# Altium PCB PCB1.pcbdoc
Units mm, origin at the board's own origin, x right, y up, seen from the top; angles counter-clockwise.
Board outline 216.66 x 148.21 mm, 2 copper layers (Top Layer, Bottom Layer); 59 components, 30 nets, 163 pads, 96 vias.
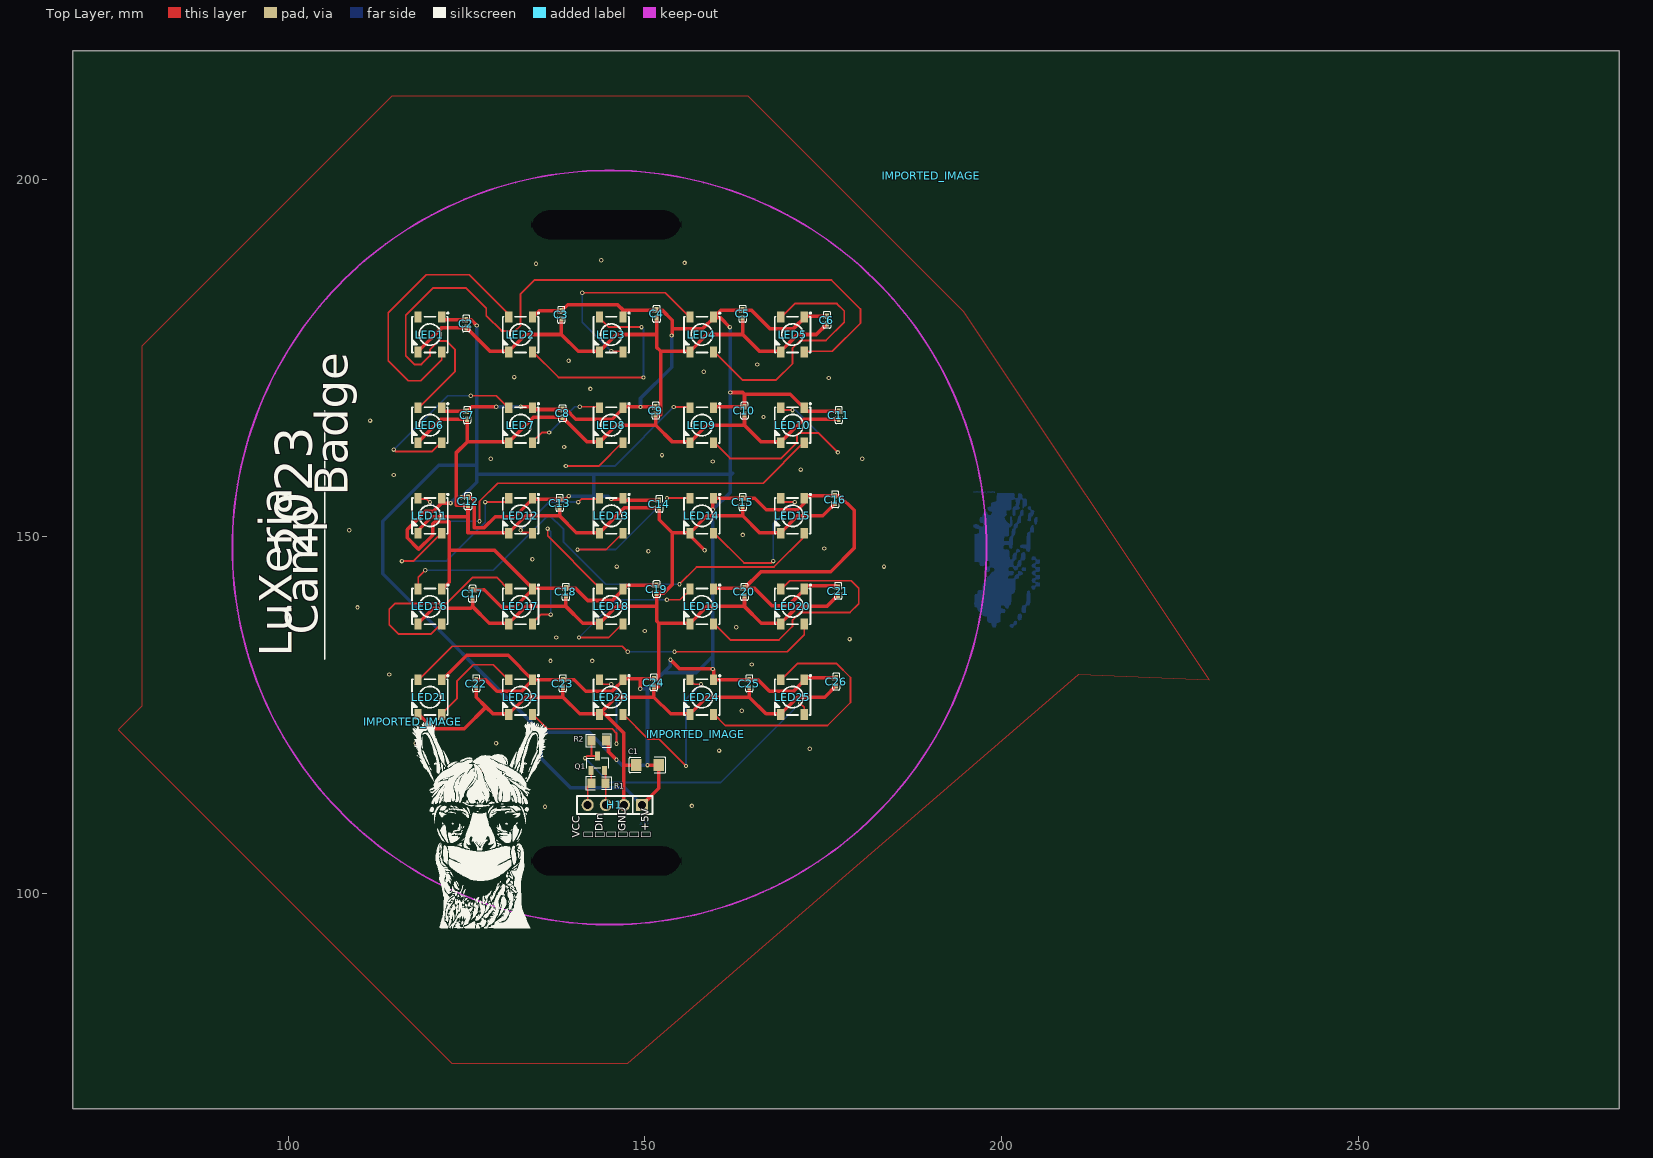
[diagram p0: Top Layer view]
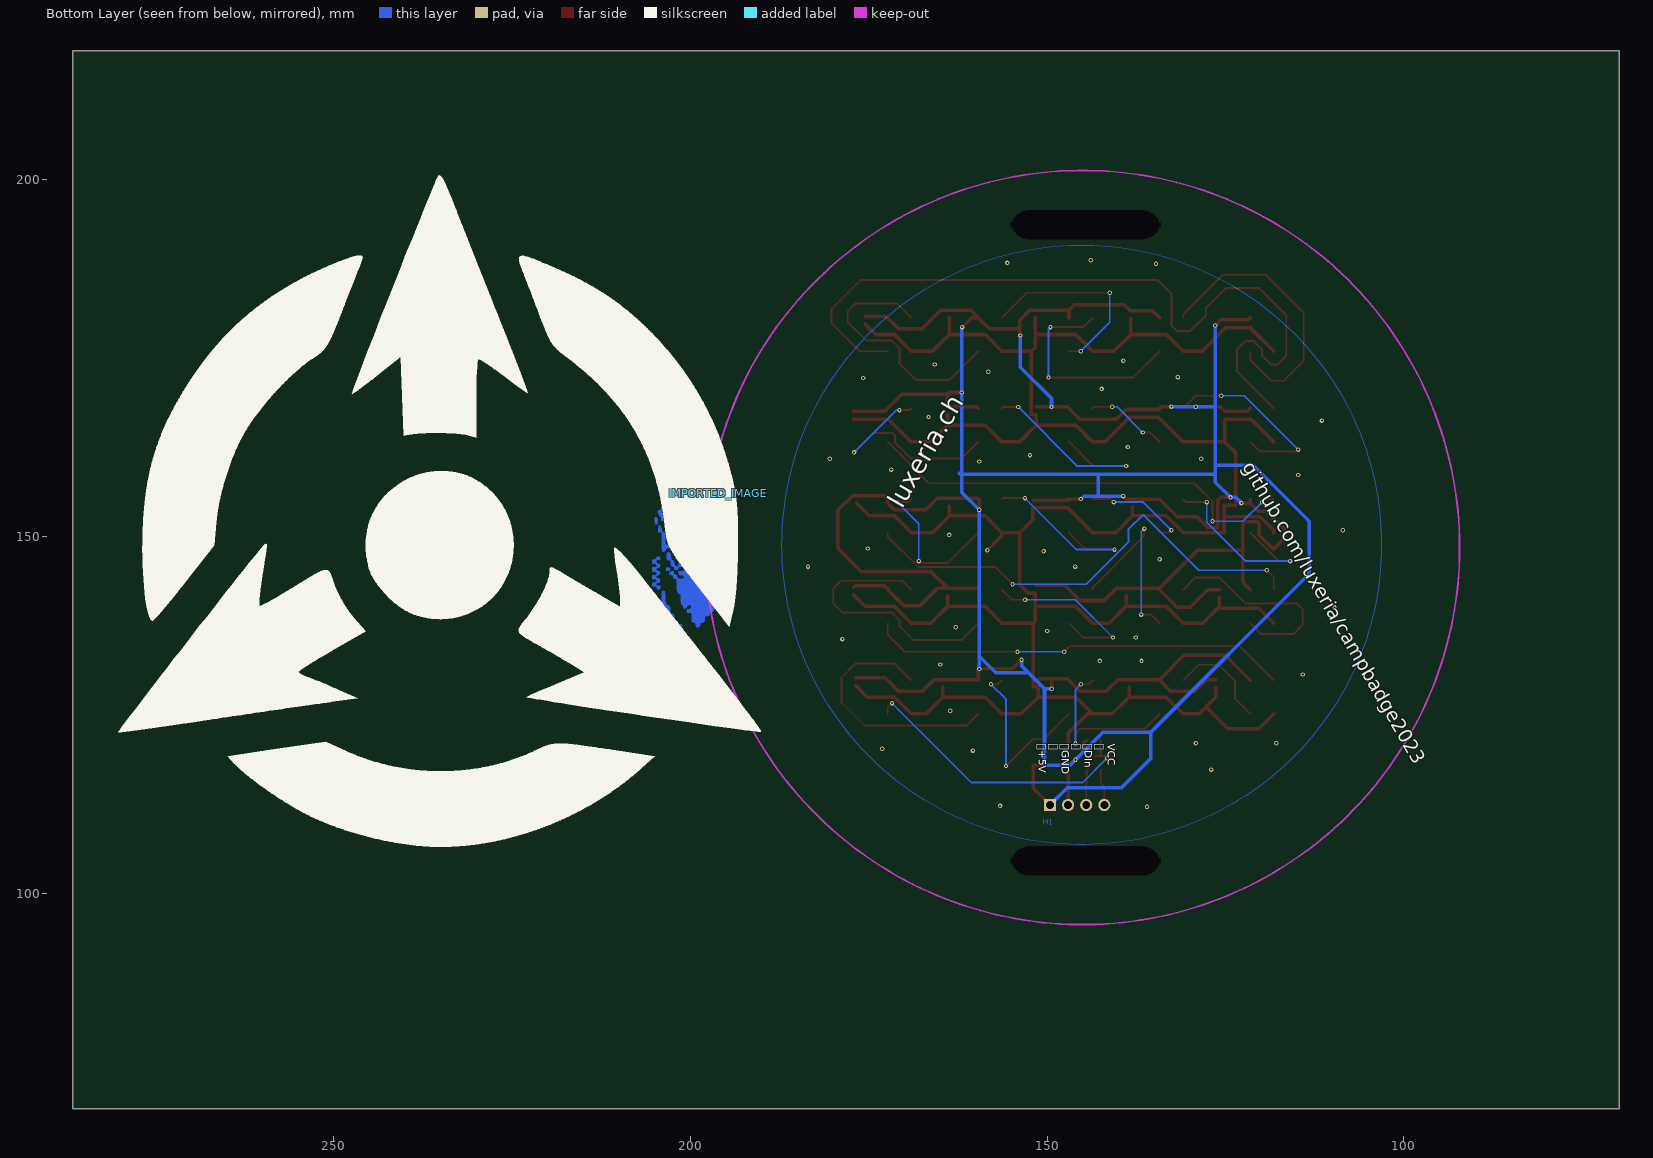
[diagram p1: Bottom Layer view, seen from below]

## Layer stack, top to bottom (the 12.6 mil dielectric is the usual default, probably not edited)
Top Layer: signal copper (thickness not stored)
Dielectric: dielectric 0.32, FR-4, Dk 4.8
Bottom Layer: signal copper (thickness not stored)

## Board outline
286.512,69.85 69.85,69.85 69.85,218.059 286.512,218.059
cut-out: 136.652,195.707 152.527,195.707 cw(c152.527,193.167) 155.067,193.167 155.067,194.183 cw(c152.527,194.183) 152.527,191.643 136.652,191.643 cw(c136.652,194.183) 134.112,194.183 134.112,193.167 cw(c136.652,193.167)
cut-out: 136.652,106.584 152.527,106.584 cw(c152.527,104.044) 155.067,104.044 155.067,105.06 cw(c152.527,105.06) 152.527,102.52 136.652,102.52 cw(c136.652,105.06) 134.112,105.06 134.112,104.044 cw(c136.652,104.044)

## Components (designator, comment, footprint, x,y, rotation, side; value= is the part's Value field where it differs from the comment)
C1 "CL31A107MQHNNNE" C1206 150.368,117.983 r0 top
C2 "CC0402KRX7R5BB104" C0402 124.968,179.832 r90 top
C3 "CC0402KRX7R5BB104" C0402 138.303,181.065 r90 top
C4 "CC0402KRX7R5BB104" C0402 151.638,181.192 r90 top
C5 "CC0402KRX7R5BB104" C0402 163.703,181.192 r90 top
C6 "CC0402KRX7R5BB104" C0402 175.514,180.34 r90 top
C7 "CC0402KRX7R5BB104" C0402 125.095,167.005 r90 top
C8 "CC0402KRX7R5BB104" C0402 138.467,167.259 r90 top
C9 "CC0402KRX7R5BB104" C0402 151.511,167.64 r90 top
C10 "CC0402KRX7R5BB104" C0402 163.957,167.64 r90 top
C11 "CC0402KRX7R5BB104" C0402 177.165,167.005 r90 top
C12 "CC0402KRX7R5BB104" C0402 125.222,154.94 r90 top
C13 "CC0402KRX7R5BB104" C0402 138.049,154.686 r90 top
C14 "CC0402KRX7R5BB104" C0402 152.019,154.559 r90 top
C15 "CC0402KRX7R5BB104" C0402 163.703,154.813 r90 top
C16 "CC0402KRX7R5BB104" C0402 176.657,155.194 r90 top
C17 "CC0402KRX7R5BB104" C0402 125.857,141.986 r90 top
C18 "CC0402KRX7R5BB104" C0402 138.938,142.24 r90 top
C19 "CC0402KRX7R5BB104" C0402 151.638,142.621 r90 top
C20 "CC0402KRX7R5BB104" C0402 163.957,142.24 r90 top
C21 "CC0402KRX7R5BB104" C0402 177.075,142.367 r90 top
C22 "CC0402KRX7R5BB104" C0402 126.365,129.413 r90 top
C23 "CC0402KRX7R5BB104" C0402 138.52,129.413 r90 top
C24 "CC0402KRX7R5BB104" C0402 151.257,129.54 r90 top
C25 "CC0402KRX7R5BB104" C0402 164.629,129.413 r90 top
C26 "CC0402KRX7R5BB104" C0402 176.821,129.667 r90 top
H1 "2.54-1*4P母" HDR-TH_4P-P2.54-V-F 145.796,112.395 r180 top
IMPORTED_IMAGE "IMPORTED_IMAGE" IMPORTED_IMAGE#1 190.113,200.573 r0 top
IMPORTED_IMAGE "IMPORTED_IMAGE" IMPORTED_IMAGE#1 117.475,124.079 r0 top
IMPORTED_IMAGE "IMPORTED_IMAGE" IMPORTED_IMAGE#1 157.099,122.301 r0 top
IMPORTED_IMAGE "IMPORTED_IMAGE" IMPORTED_IMAGE#2 196.088,156.083 r0 bottom
LED1 "WS2812C/W" LED-SMD_4P-L5.0-W5.0-TL_WS2812B-B 119.888,178.308 r270 top
LED2 "WS2812C/W" LED-SMD_4P-L5.0-W5.0-TL_WS2812B-B 132.588,178.308 r270 top
LED3 "WS2812C/W" LED-SMD_4P-L5.0-W5.0-TL_WS2812B-B 145.288,178.308 r270 top
LED4 "WS2812C/W" LED-SMD_4P-L5.0-W5.0-TL_WS2812B-B 157.988,178.308 r270 top
LED5 "WS2812C/W" LED-SMD_4P-L5.0-W5.0-TL_WS2812B-B 170.688,178.308 r270 top
LED6 "WS2812C/W" LED-SMD_4P-L5.0-W5.0-TL_WS2812B-B 119.888,165.608 r270 top
LED7 "WS2812C/W" LED-SMD_4P-L5.0-W5.0-TL_WS2812B-B 132.588,165.608 r270 top
LED8 "WS2812C/W" LED-SMD_4P-L5.0-W5.0-TL_WS2812B-B 145.288,165.608 r270 top
LED9 "WS2812C/W" LED-SMD_4P-L5.0-W5.0-TL_WS2812B-B 157.988,165.608 r270 top
LED10 "WS2812C/W" LED-SMD_4P-L5.0-W5.0-TL_WS2812B-B 170.688,165.608 r270 top
LED11 "WS2812C/W" LED-SMD_4P-L5.0-W5.0-TL_WS2812B-B 119.888,152.908 r270 top
LED12 "WS2812C/W" LED-SMD_4P-L5.0-W5.0-TL_WS2812B-B 132.588,152.908 r270 top
LED13 "WS2812C/W" LED-SMD_4P-L5.0-W5.0-TL_WS2812B-B 145.288,152.908 r270 top
LED14 "WS2812C/W" LED-SMD_4P-L5.0-W5.0-TL_WS2812B-B 157.988,152.908 r270 top
LED15 "WS2812C/W" LED-SMD_4P-L5.0-W5.0-TL_WS2812B-B 170.688,152.908 r270 top
LED16 "WS2812C/W" LED-SMD_4P-L5.0-W5.0-TL_WS2812B-B 119.888,140.208 r270 top
LED17 "WS2812C/W" LED-SMD_4P-L5.0-W5.0-TL_WS2812B-B 132.588,140.208 r270 top
LED18 "WS2812C/W" LED-SMD_4P-L5.0-W5.0-TL_WS2812B-B 145.288,140.208 r270 top
LED19 "WS2812C/W" LED-SMD_4P-L5.0-W5.0-TL_WS2812B-B 157.988,140.208 r270 top
LED20 "WS2812C/W" LED-SMD_4P-L5.0-W5.0-TL_WS2812B-B 170.688,140.208 r270 top
LED21 "WS2812C/W" LED-SMD_4P-L5.0-W5.0-TL_WS2812B-B 119.888,127.508 r270 top
LED22 "WS2812C/W" LED-SMD_4P-L5.0-W5.0-TL_WS2812B-B 132.588,127.508 r270 top
LED23 "WS2812C/W" LED-SMD_4P-L5.0-W5.0-TL_WS2812B-B 145.288,127.508 r270 top
LED24 "WS2812C/W" LED-SMD_4P-L5.0-W5.0-TL_WS2812B-B 157.988,127.508 r270 top
LED25 "WS2812C/W" LED-SMD_4P-L5.0-W5.0-TL_WS2812B-B 170.688,127.508 r270 top
Q1 "BSS138_C489349" SOT-23-3_L2.9-W1.3-P1.90-LS2.4-BR 143.383,118.237 r270 top
R1 "0805W8F1002T5E" R0805 143.494,115.443 r180 top
R2 "0805W8F1002T5E" R0805 143.526,121.412 r0 top

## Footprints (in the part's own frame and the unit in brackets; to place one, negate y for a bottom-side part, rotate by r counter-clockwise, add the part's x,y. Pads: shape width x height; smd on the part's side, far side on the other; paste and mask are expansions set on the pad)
C0402 [mm]
  rect 0.79x0.54 smd paste-100 mask+0.051: 1(-0.545,0) 2(0.545,0)
  silkscreen extent -1.17,-0.5 1.17,0.5
C1206 [mm]
  rect 1.485x1.728 smd paste-100 mask+0.051: 1(-1.593,0) 2(1.593,0)
  silkscreen extent -2.56,-1.09 2.56,1.09
HDR-TH_4P-P2.54-V-F [mm]
  rect 1.7x1.7 hole 1.1 paste+0 mask+0.051: 1(-3.81,0)
  round 1.7 hole 1.1 paste+0 mask+0.051: 2(-1.27,0) 3(1.27,0) 4(3.81,0)
  silkscreen extent -5.29,-1.27 5.29,1.27
IMPORTED_IMAGE#1 [mm]
IMPORTED_IMAGE#2 [mm]
  Top Layer region: 5.432,18.885 5.293,18.885 5.144,18.79 5.043,18.635 5.051,18.498 5.156,18.4 5.349,18.363 5.516,18.305 5.573,18.134 5.632,17.961 5.812,17.904 5.996,17.967 6.014,18.22 5.939,18.455 5.775,18.502 5.63,18.526 5.573,18.638 5.533,18.8
  Top Layer region: 573 vertices and 22 holes, not listed, extent -0.058,0 7.422,18.822
  Top Layer region: 6.667,17.714 6.432,17.789 6.282,17.775 6.197,17.714 6.159,17.575 6.151,17.33 6.197,16.948 6.426,16.871 6.572,16.886 6.656,16.949 6.696,17.088 6.708,17.33
  Top Layer region: 7.018,16.756 6.929,16.754 6.86,16.742 6.809,16.718 6.774,16.676 6.75,16.612 6.736,16.521 6.73,16.398 6.729,16.24 6.773,15.807 7.003,15.724 7.061,15.72 7.114,15.708 7.161,15.687 7.204,15.656 7.243,15.616 7.277,15.565 7.307,15.503 7.333,15.429 7.356,15.342 7.374,15.242 7.39,15.129 7.402,15.001 7.411,14.857 7.417,14.699 7.421,14.524 7.422,14.332 7.461,13.771 7.653,13.658 7.691,13.659 7.724,13.663 7.754,13.671 7.78,13.685 7.802,13.705 7.82,13.732 7.836,13.769 7.849,13.815 7.859,13.873 7.868,13.943 7.874,14.027 7.878,14.126 7.881,14.24 7.883,14.372 7.884,14.521 7.884,14.691 7.879,15.285 7.847,15.592 7.761,15.706 7.595,15.724 7.507,15.726 7.438,15.738 7.387,15.762 7.351,15.804 7.328,15.868 7.314,15.959 7.308,16.082 7.306,16.24 7.299,16.521 7.261,16.676 7.175,16.742
  Top Layer region: 8.51,13.47 8.355,13.541 8.192,13.492 8.084,13.32 8.058,13.147 8.099,13.04 8.219,12.985 8.432,12.969 8.638,12.924 8.671,12.768 8.576,12.626 8.402,12.567 8.295,12.55 8.218,12.494 8.166,12.396 8.137,12.252 8.16,11.991 8.405,11.936 8.618,11.875 8.68,11.738 8.598,11.59 8.374,11.498 8.155,11.381 8.092,11.179 8.18,10.988 8.413,10.903 8.621,10.842 8.68,10.704 8.596,10.556 8.374,10.465 8.173,10.351 8.099,10.149 8.157,9.956 8.35,9.87 8.537,9.816 8.656,9.687 8.662,9.537 8.58,9.42 8.44,9.358 8.27,9.377 8.153,9.348 8.115,9.137 8.201,8.903 8.393,8.814 8.596,8.876 8.714,9.096 8.8,9.29 9.011,9.318 9.22,9.346 9.271,9.568 9.257,9.711 9.207,9.804 9.109,9.861 8.953,9.891 8.709,9.972 8.635,10.157 8.701,10.335 8.953,10.365 9.121,10.365 9.217,10.405 9.261,10.505 9.271,10.685 9.261,10.866 9.218,10.964 9.122,11.001 8.953,10.994 8.692,11.019 8.598,11.219 8.591,11.305 8.598,11.374 8.621,11.426 8.664,11.463 8.727,11.485 8.814,11.495 8.927,11.494 9.069,11.483 9.224,11.535 9.271,11.757 9.258,11.908 9.208,11.998 9.103,12.04 8.924,12.051 8.65,12.099 8.578,12.28 8.594,12.392 8.65,12.462 8.756,12.499 8.924,12.51 9.208,12.563 9.271,12.801 9.26,12.951 9.214,13.034 9.118,13.066 8.953,13.059 8.692,13.085 8.598,13.285
  Top Layer region: 7.245,10.849 7.018,10.903 6.79,10.849 6.729,10.645 6.79,10.441 7.018,10.387 7.245,10.441 7.306,10.645
  Top Layer region: 7.773,8.24 7.624,8.243 7.422,8.149 7.327,7.948 7.292,7.819 7.22,7.74 7.094,7.7 6.894,7.69 6.576,7.644 6.497,7.46 6.516,7.344 6.584,7.274 6.725,7.239 6.96,7.231 7.422,7.231 7.422,6.37 7.458,5.652 7.64,5.509 7.699,5.503 7.749,5.485 7.792,5.452 7.829,5.402 7.86,5.333 7.888,5.243 7.913,5.13 7.936,4.993 8.037,4.608 8.18,4.476 8.298,4.522 8.346,4.634 8.352,4.723 8.368,4.851 8.391,4.999 8.419,5.15 8.432,5.453 8.188,5.509 7.884,5.509 7.884,6.894 7.88,7.688 7.851,8.096
  Top Layer region: 8.835,4.293 8.693,4.419 8.551,4.283 8.478,3.974 8.489,3.64 8.599,3.428 8.695,3.373 8.771,3.345 8.829,3.346 8.87,3.379 8.896,3.445 8.909,3.548 8.911,3.69 8.902,3.873
  Top Layer region: 7.755,3.902 7.573,3.851 7.58,3.644 7.607,3.519 7.63,3.369 7.645,3.213 7.652,3.07 7.697,2.836 7.826,2.754 7.964,2.698 7.995,2.568 7.927,2.425 7.769,2.329 7.605,2.223 7.538,2.052 7.597,1.892 7.769,1.836 7.948,1.902 8,2.128 8.045,2.346 8.198,2.387 8.353,2.422 8.44,2.569 8.429,2.798 8.341,3.043 8.218,3.225 8.098,3.26 8.029,3.321 8,3.551 7.951,3.832
LED-SMD_4P-L5.0-W5.0-TL_WS2812B-B [mm]
  rect 1.5x1 smd paste+0 mask+0.051: 1(-2.45,1.65) 2(-2.45,-1.65) 3(2.45,-1.65) 4(2.45,1.65)
  silkscreen extent -3.1,-2.5 2.5,2.6
R0805 [mm]
  rect 1.133x1.377 smd paste-100 mask+0.051: 1(-1,0) 2(1,0)
  silkscreen extent -1.76,-0.92 1.76,0.92
SOT-23-3_L2.9-W1.3-P1.90-LS2.4-BR [mm]
  rect 1.25x0.7 smd paste+0 mask+0.051: 1(1,-0.95) 2(1,0.95) 3(-1,0)
  silkscreen extent -0.73,-1.53 0.73,1.53

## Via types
v1: diameter 0.61, hole 0.305, Top Layer to Bottom Layer, 96 vias

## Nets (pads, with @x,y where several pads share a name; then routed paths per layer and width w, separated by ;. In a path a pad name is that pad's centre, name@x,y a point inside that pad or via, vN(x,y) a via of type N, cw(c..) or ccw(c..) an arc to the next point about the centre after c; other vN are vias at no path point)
$1N5916: LED21.4 LED22.2 | length 14.6
  Top Layer w0.254: LED21.4@121.538,125.158 123.698,127.318 123.698,129.776 125.964,132.042 128.754,132.042 LED22.2@130.938,129.858
$1N5969: LED22.4 LED23.2 | length 24.9
  Top Layer w0.254: LED22.4@134.238,125.158 136.333,123.063 145.415,123.063 146.016,122.462 v1(146.016,120.972) ; LED23.2@143.638,129.858 144.197,129.299 v1(145.288,129.299)
  Bottom Layer w0.254: v1(145.288,129.299) 146.016,128.571 v1(146.016,120.972)
$1N6022: LED23.4 LED24.2 | length 25.9
  Top Layer w0.254: LED23.4@146.938,125.158 150.494,121.602 152.012,121.602 v1(155.755,117.86) ; LED24.2@156.338,129.858 156.897,129.299 v1(157.873,129.299)
  Bottom Layer w0.254: v1(155.755,117.86) 155.755,127.182 v1(157.873,129.299)
$1N6075: LED24.4 LED25.2 | length 36.2
  Top Layer w0.254: LED24.4@159.638,125.158 161.271,123.525 175.585,123.525 178.816,126.756 178.816,130.257 176.878,132.195 171.374,132.195 LED25.2@169.038,129.858
$1N6454: LED16.4 LED17.2 | length 30
  Top Layer w0.254: LED16.4@121.538,137.858 120.009,136.329 115.512,136.329 114.173,137.668 114.173,139.827 114.96,140.614 122.199,140.614 125.857,144.272 129.224,144.272 LED17.2@130.938,142.558
$1N6508: LED17.4 LED18.2 | length 26.9
  Top Layer w0.254: LED17.4@134.238,137.858 135.44,139.06 v1(136.825,139.06) ; v1(136.38,151.117) 136.38,150.098 143.638,142.84 LED18.2@143.638,142.558
  Bottom Layer w0.254: v1(136.38,151.117) 136.825,150.673 v1(136.825,139.06)
$1N6562: LED18.4 LED19.2 | length 25.3
  Top Layer w0.254: v1(140.772,135.858) 144.938,135.858 LED18.4@146.938,137.858 ; v1(153.081,141.142) 154.922,141.142 LED19.2@156.338,142.558
  Bottom Layer w0.254: v1(140.772,135.858) 146.056,141.142 v1(153.081,141.142)
$1N6618: LED19.4 LED20.2 | length 37.9
  Top Layer w0.254: LED19.4@159.638,137.858 161.975,135.521 168.795,135.521 170.688,137.414 170.688,138.303 171.754,139.369 178.739,139.369 179.959,140.589 179.959,142.748 178.909,143.798 170.278,143.798 LED20.2@169.038,142.558
$1N6672: LED11.4 LED12.2 | length 27.5
  Top Layer w0.254: v1(115.951,146.558) 117.538,146.558 LED11.4@121.538,150.558 ; v1(127.634,154.829) 130.509,154.829 LED12.2@130.938,155.258
  Bottom Layer w0.254: v1(115.951,146.558) 122.164,146.558 127.634,152.028 v1(127.634,154.829)
$1N7057: LED12.4 LED13.2 | length 14.6
  Top Layer w0.254: v1(132.588,150.894) 132.924,150.558 LED12.4@134.238,150.558 ; v1(140.678,154.829) 141.107,155.258 LED13.2@143.638,155.258
  Bottom Layer w0.254: v1(132.588,150.894) 136.523,154.829 v1(140.678,154.829)
$1N7111: LED13.4 LED14.2 | length 26.2
  Top Layer w0.254: v1(140.564,148.177) 144.557,148.177 LED13.4@146.938,150.558 ; v1(153.103,155.39) 156.206,155.39 LED14.2@156.338,155.258
  Bottom Layer w0.254: v1(140.564,148.177) 145.889,148.177 v1(153.103,155.39)
$1N7165: LED14.4 LED15.2 | length 21.9
  Top Layer w0.254: LED14.4@159.638,150.558 163.892,146.304 167.729,146.304 v1(167.983,146.558) ; LED15.2@169.038,155.258 169.466,154.829 v1(170.997,154.829)
  Bottom Layer w0.254: v1(167.983,146.558) 167.983,151.815 v1(170.997,154.829)
$1N7219: LED6.4 LED7.2 | length 27.4
  Top Layer w0.254: v1(114.808,162.179) 115.062,161.925 120.205,161.925 LED6.4@121.538,163.258 ; v1(125.603,169.742) 129.154,169.742 LED7.2@130.938,167.958
  Bottom Layer w0.254: v1(114.808,162.179) 122.371,169.742 v1(125.603,169.742)
$1N7273: LED7.4 LED8.2 | length 11.5
  Top Layer w0.254: LED7.4@134.238,163.258 135.553,164.573 v1(136.589,164.573) ; v1(140.887,168.183) 143.413,168.183 LED8.2@143.638,167.958
  Bottom Layer w0.254: v1(136.589,164.573) 140.2,168.183 v1(140.887,168.183)
$1N7327: LED8.4 LED9.2 | length 30.3
  Top Layer w0.254: v1(138.938,159.878) 143.558,159.878 LED8.4@146.938,163.258 ; v1(154.043,168.163) 156.133,168.163 LED9.2@156.338,167.958
  Bottom Layer w0.254: v1(138.938,159.878) 145.758,159.878 v1(154.043,168.163)
$1N7381: LED9.4 LED10.2 | length 32.1
  Top Layer w0.254: LED9.4@159.638,163.258 161.944,160.952 169.08,160.952 171.323,163.195 171.323,164.244 171.577,164.498 174.338,164.498 v1(177.038,161.798) ; LED10.2@169.038,167.958 169.282,167.714 v1(170.688,167.714)
  Bottom Layer w0.254: v1(170.688,167.714) 171.122,167.714 v1(177.038,161.798)
$1N7435: LED1.4 LED2.2 | length 39.7
  Top Layer w0.254: LED1.4@121.538,175.958 121.538,174.751 118.618,171.831 116.84,171.831 114.046,174.625 114.046,181.356 119.38,186.69 125.373,186.69 130.938,181.125 LED2.2@130.938,180.658
$1N7489: LED2.4 LED3.2 | length 30.7
  Top Layer w0.254: LED2.4@134.238,175.958 137.902,172.294 v1(149.816,172.294) ; LED3.2@143.638,180.658 144.953,179.343 v1(149.525,179.343)
  Bottom Layer w0.254: v1(149.525,179.343) 149.816,179.052 v1(149.816,172.294)
$1N7913: LED3.4 LED4.2 | length 28.1
  Top Layer w0.254: v1(141.224,184.15) 152.846,184.15 LED4.2@156.338,180.658 ; v1(145.288,175.958) LED3.4@146.938,175.958
  Bottom Layer w0.254: v1(141.224,184.15) 141.224,180.022 v1(145.288,175.958)
$1N7967: LED4.4 LED5.2 | length 36.3
  Top Layer w0.254: LED4.4@159.638,175.958 163.638,171.958 168.402,171.958 170.688,174.244 170.688,176.403 171.754,177.469 175.37,177.469 177.927,180.026 177.927,181.61 176.902,182.635 171.015,182.635 LED5.2@169.038,180.658
$1N8459: LED5.4 LED6.2 | length 112.9
  Top Layer w0.254: LED6.2@118.238,167.958 123.418,173.138 123.418,176.194 122.193,177.419 121.113,177.419 119.888,176.194 119.888,175.311 118.694,174.117 117.703,174.117 116.508,175.311 116.508,181.024 120.291,184.807 124.958,184.807 127.788,181.977 127.788,180.949 129.921,178.816 131.826,178.816 132.588,179.578 132.588,184.023 134.493,185.928 176.149,185.928 180.213,181.864 180.213,179.912 176.259,175.958 LED5.4@172.338,175.958
$1N8515: LED10.4 LED11.2 | length 61.6
  Top Layer w0.254: LED11.2@118.238,155.258 119.455,155.258 v1(119.888,154.825) ; v1(126.83,152.139) 126.83,154.94 129.37,157.48 166.56,157.48 LED10.4@172.338,163.258
  Bottom Layer w0.254: v1(119.888,154.825) 122.575,152.139 v1(126.83,152.139)
$1N8571: LED20.4 LED21.2 | length 59
  Top Layer w0.254: LED21.2@118.238,129.858 123,134.62 146.85,134.62 v1(147.612,133.858) ; v1(154.153,133.858) 169.926,133.858 172.338,136.27 LED20.4@172.338,137.858
  Bottom Layer w0.254: v1(147.612,133.858) v1(154.153,133.858)
$1N18789: LED15.4 LED16.2 | length 67.9
  Top Layer w0.254: LED16.2@118.238,142.558 118.238,144.289 v1(119.234,145.285) ; v1(154.844,143.323) 157.255,145.735 168.074,145.735 172.338,149.999 LED15.4@172.338,150.558
  Bottom Layer w0.254: v1(119.234,145.285) 128.767,145.285 136.545,153.062 138.605,151.002 138.605,149.221 144.503,143.323 v1(154.844,143.323)
+5V: C1.2 C2.2 C3.2 C4.2 C5.2 C6.2 C7.2 C8.2 C9.2 C10.2 C11.2 C12.2 C13.2 C14.2 C15.2 C16.2 C17.2 C18.2 C19.2 C20.2 C21.2 C22.2 C23.2 C24.2 C25.2 C26.2 H1.1 LED1.1 LED2.1 LED3.1 LED4.1 LED5.1 LED6.1 LED7.1 LED8.1 LED9.1 LED10.1 LED11.1 LED12.1 LED13.1 LED14.1 LED15.1 LED16.1 LED17.1 LED18.1 LED19.1 LED20.1 LED21.1 LED22.1 LED23.1 LED24.1 LED25.1 R2.2 | length 613.9
  Top Layer w0.5: LED21.1@121.538,129.858 125.03,133.35 130.846,133.35 LED22.1 ; LED16.1@121.538,142.558 122.578,143.598 122.578,148.114 ; LED11.1@121.538,155.258 LED11.1@121.538,154.692 ; LED6.1@121.538,167.958 121.946,167.55 C7.2 125.728,168.183 v1(129.172,168.183) ; LED1.1@121.538,180.658 121.819,180.377 C2.2 125.654,180.377 v1(126.449,179.581) ; v1(122.778,154.692) LED11.1@121.538,154.692 ; v1(124.312,155.487) 125.22,155.487 C12.2 125.693,155.485 126.123,155.055 126.123,151.259 127.493,151.259 129.015,152.781 131.788,152.781 LED12.1@134.238,155.231 ; C17.2 127.49,142.531 129.94,140.081 131.761,140.081 134.238,142.558 LED17.1@134.238,142.785 ; C22.2 127.681,129.958 129.292,128.347 132.727,128.347 134.238,129.858 LED22.1 ; v1(132.588,168.207) 133.989,168.207 134.392,167.804 C8.2 138.981,167.804 140.339,166.447 145.427,166.447 147.165,168.185 v1@149.39,168.185 ; LED12.1@134.238,155.258 LED12.1@134.238,155.231 ; LED2.1@134.238,180.658 135.19,181.61 C3.2 139.192,182.499 146.176,182.499 146.938,181.737 ; v1(139.346,155.664) 138.913,155.231 C13.2 LED12.1@134.238,155.231 ; R2.2 144.907,121.031 144.907,119.849 v1(146.016,118.74) ; v1(145.288,155.256) 146.938,155.256 147.09,155.104 C14.2 ; LED3.1@146.938,180.658 146.938,181.737 ; v1(149.363,128.683) 149.363,130.085 ; v1(149.39,168.163) v1@149.39,168.185 ; H1.1 151.961,114.75 C1.2 v1(150.368,117.983) ; C24.2 149.363,130.085 ; C9.2 v1@149.39,168.185 ; C19.2 147.546,143.166 145.427,141.047 141.992,141.047 140.254,142.785 C18.2 LED17.1@134.238,142.785 ; v1(153.583,132.747) 154.878,131.452 v1(159.523,131.452) 159.638,131.336 LED24.1 ; v1(153.751,178.168) 153.823,178.24 153.823,179.147 ; v1(159.523,153.747) 159.523,155.143 159.738,155.358 C15.2 165.416,155.358 166.995,153.78 171.433,153.78 172.338,154.685 LED15.1@172.338,155.256 ; LED24.1@159.638,129.858 LED24.1 ; LED19.1@159.638,142.558 159.865,142.785 C20.2 ; LED9.1@159.638,167.958 159.865,168.185 C10.2 163.957,169.925 ; v1(161.907,179.343) 160.592,180.658 LED4.1@159.638,180.658 ; v1(161.963,170.183) 163.699,170.183 163.957,169.925 ; LED20.1@172.338,142.558 170.115,140.335 167.767,140.335 165.317,142.785 C20.2 ; LED20.1 172.809,143.129 176.858,143.129 C21.2 ; LED15.1@172.338,155.258 172.819,155.739 C16.2 177.255,155.739 179.324,153.67 179.324,148.388 176.025,145.089 166.261,145.089 C20.2 ; C6.2 172.565,180.885 170.827,179.147 167.501,179.147 164.91,181.737 C5.2 160.717,181.737 LED4.1@159.638,180.658 ; C26.2 172.692,130.212 170.827,128.347 167.474,128.347 165.863,129.958 C25.2 LED24.1 ; C11.2 172.746,167.55 170.371,169.925 163.957,169.925 ; LED11.1@121.538,154.692 120.389,153.543 119.255,153.543 116.696,150.984 116.696,149.818 118.292,148.221 120.269,150.199 120.269,151.765 120.573,152.069 122.578,152.069 122.578,148.114 ; 122.578,148.114 128.91,148.114 LED17.1@134.238,142.785 ; LED22.1 C23.2 140.092,129.958 141.736,128.314 145.395,128.314 147.165,130.085 149.363,130.085 ; 146.938,181.737 C4.2 152.4,181.737 153.823,180.314 153.823,179.147 ; 153.823,179.147 158.127,179.147 LED4.1@159.638,180.658
  Bottom Layer w0.5: v1(122.778,154.692) 123.573,155.487 v1(124.312,155.487) 126.449,157.625 126.449,158.75 ; v1(126.449,179.581) 126.449,168.183 ; v1(132.588,168.207) 132.564,168.183 v1(129.172,168.183) 126.449,168.183 ; v1(139.346,155.664) 142.735,155.664 ; v1(145.288,155.256) 144.88,155.664 142.735,155.664 ; v1(149.363,128.683) 150.368,128.683 ; v1(149.39,168.163) 149.39,169.368 153.751,173.73 v1(153.751,178.168) ; H1.1 147.193,114.808 139.573,114.808 135.509,118.872 135.509,122.555 ; v1(153.583,132.747) 153.583,131.898 152.602,130.916 ; v1(159.523,131.452) 159.523,133.23 ; v1(161.907,179.343) 161.963,179.288 v1(161.963,170.183) 161.963,159.089 ; 126.449,158.75 142.863,158.75 ; 126.449,158.75 126.449,159.985 ; 126.449,159.985 121.123,159.985 113.284,152.146 113.284,144.78 135.509,122.555 ; 126.449,159.985 126.449,168.183 ; 135.509,122.555 142.201,122.555 v1(146.016,118.74) 146.773,117.983 v1(150.368,117.983) 150.368,128.683 ; 142.735,155.664 142.863,155.792 142.863,158.75 ; 142.863,158.75 161.963,158.75 ; 150.368,128.683 152.602,130.916 ; 152.602,130.916 157.21,130.916 159.523,133.23 ; 159.523,133.23 v1(159.523,153.747) 161.963,156.186 161.963,158.75 ; 161.963,158.75 162.179,158.75 162.306,158.877 162.175,158.877 161.963,159.089 ; 161.963,158.75 161.963,159.089
DIN: H1.3 Q1.2 R1.1 | length 4.9
  Top Layer w0.254: Q1.2 144.494,117.076 R1.1 144.526,115.411 H1.3
GND: C1.1 C2.1 C3.1 C4.1 C5.1 C6.1 C7.1 C8.1 C9.1 C10.1 C11.1 C12.1 C13.1 C14.1 C15.1 C16.1 C17.1 C18.1 C19.1 C20.1 C21.1 C22.1 C23.1 C24.1 C25.1 C26.1 H1.2 LED1.3 LED2.3 LED3.3 LED4.3 LED5.3 LED6.3 LED7.3 LED8.3 LED9.3 LED10.3 LED11.3 LED12.3 LED13.3 LED14.3 LED15.3 LED16.3 LED17.3 LED18.3 LED19.3 LED20.3 LED21.3 LED22.3 LED23.3 LED24.3 LED25.3 | length 436.8
  Top Layer w0.5: LED21.3@118.238,125.158 120.333,123.063 124.685,123.063 127.748,126.125 ; LED16.3@118.238,137.858 120.334,139.954 125.603,139.954 125.857,140.208 ; LED11.3@118.238,150.558 118.238,150.877 120.142,152.781 125.095,152.781 125.222,152.908 ; LED6.3@118.238,163.258 121.44,166.46 C7.1 125.095,163.258 ; LED1.3@118.238,175.958 121.567,179.287 C2.1 128.297,175.958 130.938,175.958 133.288,178.308 138.303,178.308 ; C17.1 125.857,140.208 ; C22.1 126.365,127.508 127.748,126.125 ; C13.1 138.049,152.908 ; C3.1 138.303,178.308 ; C23.1 138.52,127.508 ; C18.1 138.938,140.208 ; H1.2 147.066,117.983 ; C1.1 147.066,117.983 ; C4.1 151.638,178.308 ; LED14.3 156.338,150.113 v1(158.369,148.082) ; C15.1 163.703,152.908 ; C5.1 163.703,178.308 ; C20.1 163.957,140.208 ; C10.1 163.957,165.608 ; C25.1 164.629,127.508 ; C6.1 174.027,178.308 171.388,178.308 169.038,175.958 166.053,175.958 163.703,178.308 ; C16.1 174.916,152.908 171.388,152.908 169.038,150.558 166.053,150.558 163.703,152.908 ; C26.1 175.207,127.508 171.388,127.508 169.038,125.158 166.979,125.158 164.629,127.508 ; C21.1 175.461,140.208 171.388,140.208 169.038,137.858 166.307,137.858 163.957,140.208 ; C11.1 172.24,166.46 169.038,163.258 166.307,163.258 163.957,165.608 ; 125.095,163.258 130.938,163.258 134.394,166.714 C8.1 141.923,163.258 143.638,163.258 145.988,165.608 151.511,165.608 ; 125.095,163.258 123.545,161.708 123.545,154.395 C12.1 125.222,152.908 ; 125.222,152.908 125.222,150.558 130.938,150.558 133.288,152.908 138.049,152.908 ; 125.857,140.208 128.207,137.858 130.938,137.858 133.288,140.208 138.938,140.208 ; 127.748,126.125 128.715,125.158 130.938,125.158 133.288,127.508 138.52,127.508 ; 138.049,152.908 140.399,150.558 143.638,150.558 147.094,154.014 C14.1 152.019,152.362 153.823,150.558 ; 138.303,178.308 140.653,175.958 143.638,175.958 145.988,178.308 151.638,178.308 ; 138.52,127.508 140.87,125.158 LED23.3@143.638,125.158 ; 138.938,140.208 141.288,137.858 143.638,137.858 145.988,140.208 151.638,140.208 ; LED23.3@143.638,125.158 145.988,127.508 151.257,127.508 ; LED23.3@143.638,125.158 144.336,125.158 147.066,122.428 147.066,117.983 ; 151.257,127.508 153.607,125.158 156.338,125.158 158.688,127.508 164.629,127.508 ; 151.257,127.508 C24.1 151.967,128.995 151.967,137.858 ; 151.511,165.608 153.861,163.258 156.338,163.258 158.688,165.608 163.957,165.608 ; 151.511,165.608 C9.1 152.221,167.095 152.221,175.958 ; 151.638,140.208 C19.1 152.617,142.076 153.823,143.282 153.823,150.558 ; 151.638,140.208 151.638,138.187 151.967,137.858 ; 151.638,178.308 151.638,176.541 152.221,175.958 ; 151.967,137.858 156.338,137.858 158.688,140.208 163.957,140.208 ; 152.221,175.958 156.338,175.958 158.688,178.308 163.703,178.308 ; 153.823,150.558 156.338,150.558 158.688,152.908 163.703,152.908
  other v1: 136.017,112.141 156.591,112.268 127,117.348 160.401,120.015 173.101,120.269 117.91,121.031 129.159,121.031 163.576,125.603 114.173,130.683 164.973,132.08 136.779,132.588 142.624,132.588 178.689,135.636 137.579,135.858 149.987,136.779 162.814,137.287 109.728,140.081 146.05,145.796 183.515,145.796 134.239,146.812 150.495,147.955 175.133,148.336 163.703,150.241 108.585,150.876 114.808,158.623 171.831,159.385 159.512,160.528 128.397,160.909 180.467,160.909 152.4,161.417 138.684,162.56 111.506,166.243 166.624,166.751 142.367,170.688 175.768,172.212 131.699,172.339 158.242,173.101 165.735,174.117 139.319,174.625 134.747,188.214 155.575,188.341 143.891,188.722
LEDIN: LED25.4 Q1.3 R2.1 | length 42
  Top Layer w0.254: v1(141.619,118.954) 141.902,119.237 142.526,119.237 ; R2.1 142.526,119.237 ; Q1.3 142.526,119.237 ; v1(171.736,126.669) 172.338,126.067 LED25.4@172.338,125.158
  Bottom Layer w0.254: v1(141.619,118.954) 145.026,115.547 160.613,115.547 v1(171.736,126.669)
VCC: H1.4 Q1.1 R1.2 | length 5.1
  Top Layer w0.254: H1.4 141.986,114.935 R1.2 142.494,117.176 Q1.1
"": LED1.2

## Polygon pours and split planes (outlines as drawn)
GND on Bottom Layer (solid, pour order 2): 187.161,148.844 ccw(c145.161,148.844) 103.161,148.844 ccw(c145.161,148.844)
GND on Top Layer (solid, pour order 1): 164.465,211.709 114.554,211.709 79.502,176.657 79.502,126.238 76.2,122.936 122.936,76.2 147.574,76.2 210.766,130.743 229.108,129.921 194.691,181.483

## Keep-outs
Board Outline Layer:
  circle w0.254 net "": c145.034,148.463 r52.832

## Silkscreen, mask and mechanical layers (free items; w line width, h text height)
Top Silkscreen Layer:
  lines w0.254 net "": 105.156,132.842 105.156,167.64
  text "Badge" at 108.37,155.745 h4.58 r90
  text "2023" at 103.38,147.157 h5.19 r90
  text "Camp" at 104.193,136.228 h4.53 r90
  text "LuXeria" at 100.51,133.146 h4.53 r90
  text "VCC /   /  DIn /   /  GND /   /  +5V" at 150.565,107.776 h1.08 r90
Bottom Silkscreen Layer:
  text "github.com/luxeria/campbadge2023" at 122.709,159.77 h1.95 r60
  text "luxeria.ch" at 170.298,153.739 h2.6 r300
  text "VCC /   /  DIn /   /  GND /   /  +5V" at 151.187,120.951 h1.08 r90
Mechanical Layer:
  lines w0.025 net "": 134.112,104.044 134.112,105.06 ccw(c136.652,105.06) 136.652,102.52 152.527,102.52 ccw(c152.527,105.06) 155.067,105.06 155.067,104.044 ccw(c152.527,104.044) 152.527,106.584 136.652,106.584 ccw(c136.652,104.044) 134.112,104.044 ; 134.112,193.167 134.112,194.183 ccw(c136.652,194.183) 136.652,191.643 152.527,191.643 ccw(c152.527,194.183) 155.067,194.183 155.067,193.167 ccw(c152.527,193.167) 152.527,195.707 136.652,195.707 ccw(c136.652,193.167) 134.112,193.167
